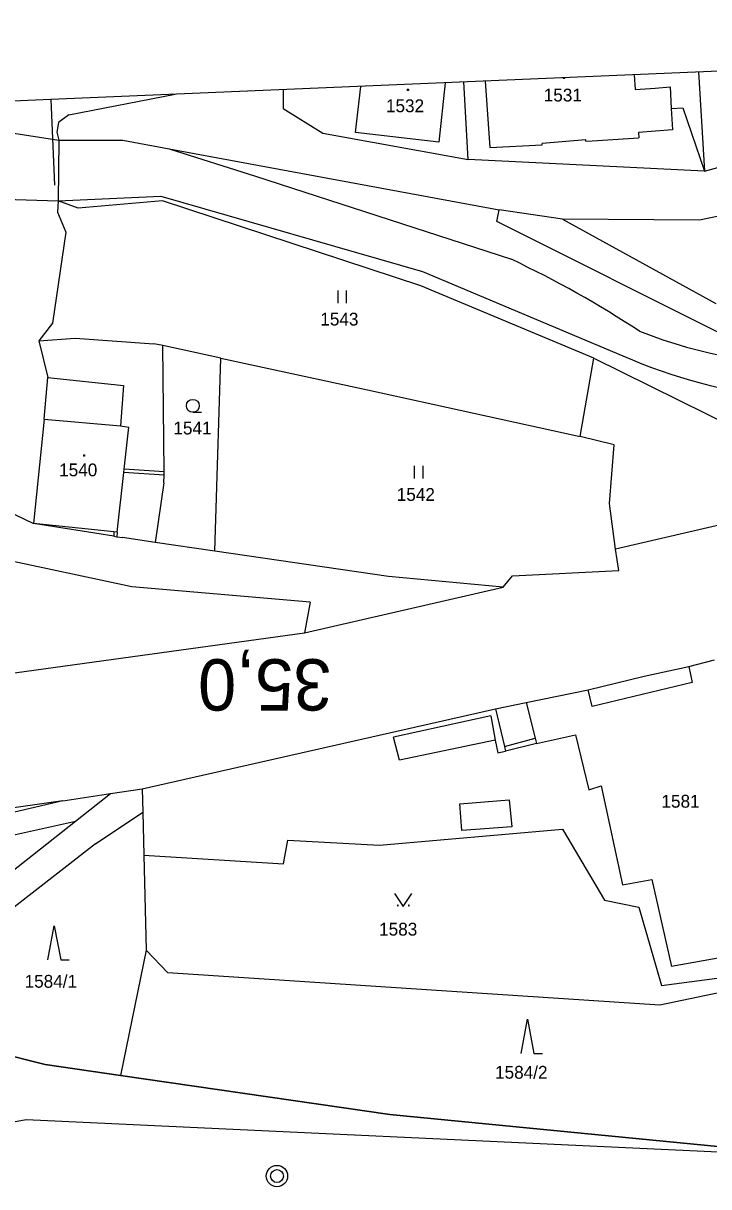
# Model space of a CAD drawing. Extents: x -806456 to -805395, y -1150847 to -1150506.
# Drawn here: x -805830 to -805749.9, y -1150650.9 to -1150515 of the extents above; entities that cross this region are included whole.
import ezdxf

# ---------------------------------------------------------------- set-up
doc = ezdxf.new("R2010")
doc.units = 0
for name, color, linetype in [('Default', 7, 'Continuous'), ('formát', 7, 'Continuous'), ('kilometráž - vrstava 7', 7, 'Continuous'), ('kn_celek - Cisla pozemkovych parcel', 7, 'Continuous'), ('kn_celek - Cisla stavebnich parcel', 7, 'Continuous'), ('kn_celek - Hranice parcel', 7, 'Continuous'), ('kn_celek - Vnitrni kresby', 7, 'Continuous'), ('kn_celek - Znacky budov', 7, 'Continuous'), ('kn_celek - Znacky kultur', 7, 'Continuous'), ('plochy - SZDC', 7, 'Continuous'), ('PSR_C2_2_trasa_Vimperk - Kabelová trasa', 7, 'Continuous')]:
    doc.layers.add(name, color=color, linetype=linetype)

# ---------------------------------------------------------------- blocks, each defined once
blk = doc.blocks.new('304')
at = {"layer": 'Default'}
blk.add_line((-0.1, 0), (9.9, 0), dxfattribs=at)
blk.add_circle((-0.1, 7.5), 7.5, dxfattribs=at)
blk = doc.blocks.new('306')
at = {"layer": 'Default'}
for p, q in [((-5.2, 0), (-5.2, 15)), ((4.8, 0), (4.8, 15))]:
    blk.add_line(p, q, dxfattribs=at)
blk = doc.blocks.new('314')
at = {"layer": 'Default'}
for p, q in [((-10, 15), (0, 0)), ((0, 0), (10, 15))]:
    blk.add_line(p, q, dxfattribs=at)
for centre, start, end in [((-6.2, 1), 360, 180), ((-6.2, 1), 180, 360), ((6.6, 1), 0, 180), ((6.6, 1), 180, 0)]:
    blk.add_arc(centre, 0.5, start, end, dxfattribs=at)
blk = doc.blocks.new('308')
at = {"layer": 'Default'}
for p, q in [((-7.5, 0.2), (0, 40.2)), ((0, 40.2), (7.5, 0.2)), ((7.5, 0.2), (17.5, 0.2))]:
    blk.add_line(p, q, dxfattribs=at)
blk = doc.blocks.new('402')
at = {"layer": 'Default'}
for p, q in [((-0.8, 0.8), (0.7, 0.8)), ((-0.8, 0.8), (-0.8, -0.7)), ((0.7, 0.8), (0.7, -0.7)), ((0.7, -0.7), (-0.8, -0.7))]:
    blk.add_line(p, q, dxfattribs=at)

msp = doc.modelspace()

# ---------------------------------------------------------------- linework, layer by layer
at = {"layer": 'Default'}
for p, q in [((-805766.88, -1150521.33), (-805766.88, -1150521.43)), ((-805766.73, -1150521.43), (-805766.88, -1150521.43)), ((-805766.73, -1150521.33), (-805766.73, -1150521.43))]:
    msp.add_line(p, q, dxfattribs=at)
at = {"layer": 'formát'}
for p, q in [((-805617.02, -1150514.97), (-805826.83, -1150523.88)), ((-805826.83, -1150523.88), (-806456.26, -1150550.6)), ((-805826.83, -1150523.88), (-805826.4, -1150533.87))]:
    msp.add_line(p, q, dxfattribs=at)
at = {"layer": 'kilometráž - vrstava 7'}
for radius in [1.25, 0.752]:
    msp.add_circle((-805800.37, -1150649.68), radius, dxfattribs=at)
at = {"layer": 'kn_celek - Hranice parcel'}
for p, q in [((-805758.6, -1150520.98), (-805758.48, -1150522.69)), ((-805751.08, -1150520.66), (-805750.38, -1150532.24)), ((-805799.65, -1150522.72), (-805799.64, -1150524.94)), ((-805778.02, -1150530.87), (-805778.5, -1150521.82)), ((-805758.48, -1150522.69), (-805756.12, -1150522.55)), ((-805756.12, -1150522.55), (-805754.38, -1150522.41)), ((-805754.38, -1150522.41), (-805754.25, -1150524.91)), ((-805824.69, -1150525.65), (-805812.27, -1150523.26)), ((-805799.64, -1150524.94), (-805795.01, -1150527.82)), ((-805754.25, -1150524.91), (-805752.89, -1150524.85)), ((-805752.89, -1150524.85), (-805750.38, -1150532.24)), ((-805750.38, -1150532.24), (-805722.27, -1150524.52)), ((-805825.91, -1150526.55), (-805826.1, -1150527.71)), ((-805824.69, -1150525.65), (-805825.91, -1150526.55)), ((-805832.14, -1150527.65), (-805825.89, -1150528.63)), ((-805826.1, -1150527.71), (-805825.89, -1150528.63)), ((-805795.01, -1150527.82), (-805778.02, -1150530.87)), ((-805825.89, -1150528.63), (-805818.41, -1150528.63)), ((-805818.41, -1150528.63), (-805812.98, -1150529.65)), ((-805812.98, -1150529.65), (-805774.4, -1150536.77)), ((-805750.38, -1150532.24), (-805778.02, -1150530.87)), ((-805734.94, -1150534.67), (-805750.97, -1150537.97)), ((-805832.18, -1150535.52), (-805825.94, -1150535.7)), ((-805825.94, -1150535.7), (-805826.04, -1150537.04)), ((-805823.62, -1150536.56), (-805825.94, -1150535.7)), ((-805813.77, -1150535.7), (-805823.62, -1150536.56)), ((-805783.53, -1150545.65), (-805813.77, -1150535.7)), ((-805826.04, -1150537.04), (-805825.04, -1150539.39)), ((-805774.64, -1150538.14), (-805774.4, -1150536.77)), ((-805766.96, -1150537.88), (-805774.4, -1150536.77)), ((-805747.87, -1150551.52), (-805774.64, -1150538.14)), ((-805750.97, -1150537.97), (-805766.96, -1150537.88)), ((-805766.96, -1150537.88), (-805749.05, -1150547.7)), ((-805825.04, -1150539.39), (-805826.63, -1150550)), ((-805763.31, -1150554.09), (-805783.53, -1150545.65)), ((-805826.63, -1150550), (-805828.22, -1150552.09)), ((-805828.22, -1150552.09), (-805823.96, -1150551.76)), ((-805828.22, -1150552.09), (-805827.15, -1150556.35)), ((-805823.96, -1150551.76), (-805814.75, -1150552.42)), ((-805813.72, -1150552.64), (-805814.75, -1150552.42)), ((-805813.54, -1150567.38), (-805813.72, -1150552.64)), ((-805806.95, -1150554.1), (-805813.72, -1150552.64)), ((-805807.63, -1150576.64), (-805806.95, -1150554.1)), ((-805806.95, -1150554.1), (-805789.77, -1150557.81)), ((-805764.9, -1150563.26), (-805763.31, -1150554.09)), ((-805763.31, -1150554.09), (-805746.44, -1150562.43)), ((-805827.58, -1150561.23), (-805827.15, -1150556.35)), ((-805789.77, -1150557.81), (-805764.9, -1150563.26)), ((-805827.58, -1150561.23), (-805828.85, -1150573.42)), ((-805760.95, -1150564.22), (-805764.9, -1150563.26)), ((-805761.47, -1150571.1), (-805760.95, -1150564.22)), ((-805717.02, -1150566.27), (-805760.78, -1150576.44)), ((-805813.56, -1150567.78), (-805813.54, -1150567.38)), ((-805840.43, -1150567.9), (-805828.85, -1150573.42)), ((-805813.6, -1150568.68), (-805814.61, -1150575.63)), ((-805813.6, -1150568.68), (-805813.56, -1150567.78)), ((-805760.78, -1150576.44), (-805761.47, -1150571.1)), ((-805819.46, -1150574.91), (-805828.85, -1150573.42)), ((-805819.46, -1150574.91), (-805819.1, -1150574.97)), ((-805819.1, -1150574.97), (-805818.45, -1150575.07)), ((-805814.61, -1150575.63), (-805818.45, -1150575.07)), ((-805807.63, -1150576.64), (-805814.61, -1150575.63)), ((-805817.33, -1150580.82), (-805834.82, -1150577.09)), ((-805787.33, -1150579.6), (-805807.63, -1150576.64)), ((-805760.39, -1150578.91), (-805760.78, -1150576.44)), ((-805773.9, -1150580.85), (-805787.33, -1150579.6)), ((-805773.9, -1150580.85), (-805772.84, -1150579.54)), ((-805772.84, -1150579.54), (-805760.39, -1150578.91)), ((-805796.5, -1150582.61), (-805817.33, -1150580.82)), ((-805797.14, -1150586.21), (-805773.9, -1150580.85)), ((-805796.5, -1150582.61), (-805797.14, -1150586.21)), ((-805890.43, -1150599.04), (-805797.14, -1150586.21)), ((-805752.19, -1150590.12), (-805749.18, -1150589.34)), ((-805757.41, -1150591.25), (-805752.19, -1150590.12)), ((-805763.97, -1150592.86), (-805757.41, -1150591.25)), ((-805771.22, -1150594.35), (-805763.97, -1150592.86)), ((-805774.8, -1150595.09), (-805771.22, -1150594.35)), ((-805786.36, -1150597.7), (-805774.8, -1150595.09)), ((-805816.14, -1150604.42), (-805786.36, -1150597.7)), ((-805825.39, -1150605.82), (-805819.83, -1150604.98)), ((-805823.93, -1150608.21), (-805819.83, -1150604.98)), ((-805819.83, -1150604.98), (-805816.14, -1150604.42)), ((-805816.14, -1150604.42), (-805816.07, -1150607.16)), ((-805825.39, -1150605.82), (-805889.59, -1150614.88)), ((-805825.39, -1150605.82), (-805838.83, -1150608.98)), ((-805838.44, -1150611.4), (-805823.93, -1150608.21)), ((-805834.72, -1150616.72), (-805823.93, -1150608.21)), ((-805821.59, -1150610.86), (-805816.07, -1150607.16)), ((-805816.07, -1150607.16), (-805815.94, -1150612.17)), ((-805788.39, -1150611.01), (-805766.99, -1150609.13)), ((-805766.99, -1150609.13), (-805762.06, -1150617.45)), ((-805821.59, -1150610.86), (-805838.24, -1150623.79)), ((-805799.59, -1150613.21), (-805799.09, -1150610.41)), ((-805799.09, -1150610.41), (-805788.39, -1150611.01)), ((-805815.94, -1150612.17), (-805815.66, -1150623.29)), ((-805815.94, -1150612.17), (-805799.59, -1150613.21)), ((-805762.06, -1150617.45), (-805758.03, -1150618.25)), ((-805758.03, -1150618.25), (-805755.38, -1150627.4)), ((-805815.66, -1150623.29), (-805818.65, -1150637.92)), ((-805813.14, -1150625.94), (-805815.66, -1150623.29)), ((-805755.61, -1150629.72), (-805813.14, -1150625.94)), ((-805736.87, -1150625.78), (-805755.61, -1150629.72)), ((-805755.38, -1150627.4), (-805738.46, -1150625.19)), ((-805845.04, -1150632.24), (-805827.46, -1150636.65)), ((-805827.46, -1150636.65), (-805818.65, -1150637.92)), ((-805818.65, -1150637.92), (-805787.18, -1150642.48)), ((-805787.18, -1150642.48), (-805727.67, -1150648.26))]:
    msp.add_line(p, q, dxfattribs=at)
at = {"layer": 'kn_celek - Vnitrni kresby'}
for p, q in [((-805791.19, -1150527.74), (-805790.57, -1150522.34)), ((-805780.68, -1150521.92), (-805781.44, -1150528.87)), ((-805776.02, -1150521.72), (-805775.47, -1150529.5)), ((-805754.25, -1150524.91), (-805754.11, -1150527.44)), ((-805781.44, -1150528.87), (-805791.19, -1150527.74)), ((-805754.11, -1150527.44), (-805758.08, -1150527.74)), ((-805758.08, -1150527.74), (-805758.03, -1150528.34)), ((-805825.89, -1150528.63), (-805825.94, -1150535.7)), ((-805775.47, -1150529.5), (-805769.36, -1150529.17)), ((-805764.24, -1150528.6), (-805769.37, -1150529.02)), ((-805769.36, -1150529.17), (-805769.37, -1150529.02)), ((-805764.23, -1150528.75), (-805764.24, -1150528.6)), ((-805764.23, -1150528.75), (-805763.5, -1150528.72)), ((-805763.5, -1150528.72), (-805758.03, -1150528.34)), ((-805812.98, -1150529.65), (-805802.89, -1150532.84)), ((-805802.89, -1150532.84), (-805772.94, -1150542.55)), ((-805825.94, -1150535.7), (-805813.93, -1150535.16)), ((-805813.93, -1150535.16), (-805783.35, -1150543.98)), ((-805783.35, -1150543.98), (-805759.9, -1150553.82)), ((-805827.15, -1150556.35), (-805818.3, -1150557.3)), ((-805818.3, -1150557.3), (-805818.68, -1150562.02)), ((-805827.58, -1150561.23), (-805818.68, -1150562.02)), ((-805818.68, -1150562.02), (-805817.7, -1150562.17)), ((-805818.24, -1150567.08), (-805817.7, -1150562.17)), ((-805819.04, -1150574.45), (-805818.28, -1150567.48)), ((-805818.28, -1150567.48), (-805818.24, -1150567.08)), ((-805813.56, -1150567.78), (-805818.28, -1150567.48)), ((-805813.54, -1150567.38), (-805818.24, -1150567.08)), ((-805819.44, -1150574.41), (-805828.85, -1150573.42)), ((-805819.44, -1150574.41), (-805819.46, -1150574.91)), ((-805819.04, -1150574.45), (-805819.44, -1150574.41)), ((-805819.04, -1150574.45), (-805819.1, -1150574.97)), ((-805752.19, -1150590.12), (-805751.81, -1150591.99)), ((-805751.81, -1150591.99), (-805763.52, -1150594.81)), ((-805763.52, -1150594.81), (-805763.97, -1150592.86)), ((-805771.22, -1150594.35), (-805770.18, -1150598.51)), ((-805775.36, -1150595.88), (-805786.72, -1150598.39)), ((-805775.36, -1150595.88), (-805774.83, -1150598.73)), ((-805774.8, -1150595.09), (-805773.76, -1150599.49)), ((-805786.04, -1150601.08), (-805786.72, -1150598.39)), ((-805774.83, -1150598.73), (-805786.04, -1150601.08)), ((-805774.83, -1150598.73), (-805774.54, -1150600.22)), ((-805773.76, -1150599.49), (-805770.18, -1150598.51)), ((-805770.18, -1150598.51), (-805770.03, -1150599.12)), ((-805770.03, -1150599.12), (-805765.45, -1150598.1)), ((-805765.45, -1150598.1), (-805763.9, -1150604.54)), ((-805774.54, -1150600.22), (-805773.64, -1150600.01)), ((-805773.76, -1150599.49), (-805773.64, -1150600.01)), ((-805770.03, -1150599.12), (-805773.64, -1150600.01)), ((-805763.9, -1150604.54), (-805762.47, -1150604.06)), ((-805762.47, -1150604.06), (-805759.95, -1150615.66)), ((-805778.99, -1150606.18), (-805773.21, -1150605.7)), ((-805773.21, -1150605.7), (-805772.9, -1150608.86)), ((-805778.73, -1150609.28), (-805778.99, -1150606.18)), ((-805772.9, -1150608.86), (-805778.73, -1150609.28)), ((-805759.95, -1150615.66), (-805756.52, -1150615.03)), ((-805756.52, -1150615.03), (-805754.24, -1150625.19)), ((-805745.04, -1150623.53), (-805754.24, -1150625.19))]:
    msp.add_line(p, q, dxfattribs=at)
for centre, radius, start, end in [((-805826.11, -1150654.8), 124.2, 56.7237, 64.6552), ((-805826.11, -1150654.8), 124.2, 56.7237, 64.6552), ((-805736.27, -1150495.31), 59.73, 248.7048, 270.9655), ((-805736.27, -1150495.31), 59.73, 248.7048, 270.9655), ((-805735.67, -1150499.41), 59.56, 245.9907, 282.7701), ((-805735.67, -1150499.41), 59.56, 245.9907, 282.7701)]:
    msp.add_arc(centre, radius, start, end, dxfattribs=at)
at = {"layer": 'plochy - SZDC'}
for p, q in [((-805827.46, -1150636.65), (-805845.04, -1150632.24)), ((-805818.65, -1150637.92), (-805827.46, -1150636.65)), ((-805787.18, -1150642.48), (-805818.65, -1150637.92)), ((-805727.67, -1150648.26), (-805787.18, -1150642.48))]:
    msp.add_line(p, q, dxfattribs=at)
at = {"layer": 'PSR_C2_2_trasa_Vimperk - Kabelová trasa'}
msp.add_lwpolyline([(-805871.58, -1150644.84), (-805841.67, -1150645.26), (-805829.69, -1150643.07), (-805746.23, -1150646.95), (-805734.34, -1150648.12), (-805727.43, -1150648.58), (-805708.99, -1150648.44)], dxfattribs=at)

# ---------------------------------------------------------------- block references
at = {"layer": 'kn_celek - Znacky budov', "xscale": 0.1, "yscale": 0.10000000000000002}
for p in [(-805785.06, -1150522.74), (-805822.93, -1150565.49)]:
    msp.add_blockref('402', p, dxfattribs=at)
at = {"layer": 'kn_celek - Znacky kultur', "xscale": 0.1, "yscale": 0.10000000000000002}
for name, p in [('306', (-805792.7, -1150547.69)), ('304', (-805810.2, -1150560.42)), ('306', (-805783.76, -1150568.18)), ('314', (-805785.61, -1150618.16)), ('308', (-805826.41, -1150624.44)), ('308', (-805771.07, -1150635.38))]:
    msp.add_blockref(name, p, dxfattribs=at)

# ---------------------------------------------------------------- texts
at = {"layer": 'kilometráž - vrstava 7'}
msp.add_text('35,0', height=6, rotation=180, dxfattribs=at).set_placement((-805793.98, -1150589.28))
at = {"layer": 'kn_celek - Cisla pozemkovych parcel'}
for s, p in [('1543', (-805795.3, -1150550.29)), ('1541', (-805812.48, -1150563.02)), ('1542', (-805786.36, -1150570.78)), ('1581', (-805755.4, -1150606.63)), ('1583', (-805788.42, -1150621.58)), ('1584/1', (-805829.88, -1150627.67)), ('1584/2', (-805774.86, -1150638.3))]:
    msp.add_text(s, height=1.5, dxfattribs=at).set_placement(p)
at = {"layer": 'kn_celek - Cisla stavebnich parcel'}
for s, p in [('1531', (-805769.17, -1150524.11)), ('1532', (-805787.62, -1150525.36)), ('1540', (-805825.84, -1150567.91))]:
    msp.add_text(s, height=1.5, dxfattribs=at).set_placement(p)

doc.saveas('drawing.dxf')
